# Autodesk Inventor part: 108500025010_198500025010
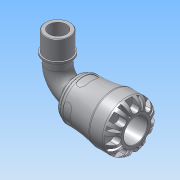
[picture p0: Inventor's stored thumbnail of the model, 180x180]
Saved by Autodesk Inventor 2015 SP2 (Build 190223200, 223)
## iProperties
Created: 2016-12
Part Number: 108500025010_198500025010
Material: PVC-Piping
Description: PLASSON 90° ELBOW WITH THREADED MALE OFFTAKE 25X1" SERIES 1
Document SubType Name: Modeling
Designer: KIM
Mass: 664.223 g
Surface Area: 733.008 cm^2
Volume: 474.445 cm^3
Density: 1.4 g/cm^3
Appearance: Smooth - White
Author: KIM
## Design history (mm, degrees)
derived "1085.ipt"
feature "Solid1::1085.ipt"
tag "TaggingFeature1"
body "Solid1"
other parameters: "d1" = 20.16, "d2" = 25, "d3" = 31.25, "d4" = 47, "d8" = 39.95, "d13" = 6.3, "d14" = 6.3, "d15" = 0, "d17" = 360 deg, "d19" = 8 deg, "d20" = 0.5, "d21" = 0.5, "d22" = 8 deg, "d24" = 0, "d26" = 360 deg, "d33" = 4.7, "d43" = 36.66, "d51" = 0.47, "d54" = 8.75, "d55" = 5.5, "d57" = 12.348, "d58" = 0, "d74" = 0, "d78" = 48, "d82" = 0.5, "d115" = 360 deg, "d207" = 90 deg, "d228" = 7.4375, "d247" = 0.94, "d248" = 2.88, "d268" = 21.9725, "d269" = 2.88, "d270" = 74, "d276" = 33.249, "d277" = 19, "d278" = 36.5739, "d279" = 47, "d280" = 20.9, "d281" = 4.98735, "d283" = 29.9241, "d286" = 0, "d287" = 0, "d288" = 23.2743, "d290" = 3.36795, "d292" = 30 deg, "d_" = 25, "E_" = 47, "l_" = 48, "A_" = 74, "A_1" = 47, "l_2" = 19, "R_" = 33.249, "d9" = 7.875, "d11" = 47, "d12" = 31.25, "d289" = 23.2743
